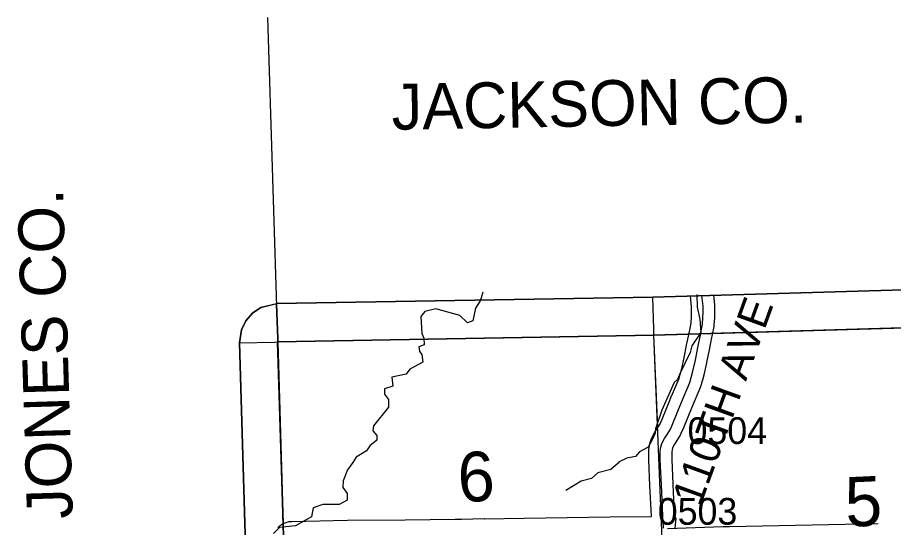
# Model space of a CAD drawing. Extents: x 128.7 to 185.5, y -21.4 to 12.6.
# Drawn here: x 133.107 to 135.402, y 3.861 to 5.197 of the extents above; entities that cross this region are included whole.
import ezdxf

# ---------------------------------------------------------------- set-up
doc = ezdxf.new("R2010")
doc.units = 0
for name, color, linetype in [('tdCoClipBndry', 7, 'Continuous'), ('tdCoCoBndry', 7, 'Continuous'), ('tdCoCoBndryPart', 7, 'Continuous'), ('tdCoCoBndryTxt', 7, 'Continuous'), ('tdCoHydroRiver', 7, 'Continuous'), ('tdCoSecRdNmbr', 7, 'Continuous'), ('tdCoSecRdTxt', 7, 'Continuous'), ('tdCoSecRteBand', 7, 'Continuous'), ('tdCoSecRteCL', 7, 'Continuous'), ('tdCoSectLine', 7, 'Continuous'), ('tdCoSectLinePart', 7, 'Continuous'), ('tdCoSectNmbr', 7, 'Continuous'), ('tdCoSurfGravel', 7, 'Continuous'), ('tdCoSurfLNO', 7, 'Continuous'), ('tdCoTwpBndryShd', 7, 'Continuous')]:
    doc.layers.add(name, color=color, linetype=linetype)

msp = doc.modelspace()

# ---------------------------------------------------------------- linework, layer by layer
at = {"layer": 'tdCoClipBndry'}
msp.add_lwpolyline([(134.0612, -7.7025), (133.8962, -2.6807), (133.6887, 4.3446), (133.6938, 4.3792), (133.7053, 4.4028), (133.7226, 4.4226), (133.7445, 4.4372), (133.7868, 4.4475), (134.771, 4.4649), (135.7559, 4.4935), (136.7866, 4.5129), (139.7725, 4.5879), (146.7594, 4.806), (147.7608, 4.8492), (149.7557, 4.9088), (150.75, 4.946), (153.7332, 5.0633)], dxfattribs=at)
at = {"layer": 'tdCoCoBndry'}
for p, q in [((133.7889, 4.3556), (133.7861, 4.4473)), ((133.7861, 4.4473), (133.7889, 4.3556)), ((134.7737, 4.365), (135.7592, 4.3936)), ((135.7592, 4.3936), (134.7737, 4.365)), ((133.789, 4.3475), (134.7737, 4.365)), ((134.7737, 4.365), (133.789, 4.3475)), ((133.789, 4.3475), (133.7889, 4.3556)), ((133.7889, 4.3556), (133.789, 4.3475)), ((133.8192, 3.3421), (133.789, 4.3475)), ((133.789, 4.3475), (133.8192, 3.3421))]:
    msp.add_line(p, q, dxfattribs=at)
for points in [[(139.7725, 4.5879), (136.7866, 4.5129), (135.7559, 4.4935), (134.771, 4.4649), (133.7868, 4.4475), (133.7861, 4.4473), (133.7889, 4.3556), (133.789, 4.3475), (134.7737, 4.365), (135.7592, 4.3936), (135.7859, 4.3937), (136.7735, 4.4131), (136.7891, 4.4129), (137.7728, 4.4375)], [(133.7886, 4.3475), (134.7733, 4.365), (135.7588, 4.3936), (135.7855, 4.3937), (136.7732, 4.4131), (136.7888, 4.4129), (137.7724, 4.4375)], [(134.1615, -7.6994), (134.1297, -6.7029), (134.1294, -6.6932), (134.095, -5.6895), (134.0611, -4.6883), (134.0307, -3.6816), (133.9965, -2.6778), (133.9676, -1.6731), (133.9395, -0.6703), (133.9071, 0.3357), (133.8784, 1.3376), (133.8476, 2.341), (133.8192, 3.3421), (133.789, 4.3475), (134.7737, 4.365), (135.7592, 4.3936), (135.7859, 4.3937), (136.7735, 4.4131), (136.7891, 4.4129), (137.7728, 4.4375)], [(133.7886, 4.3475), (133.8188, 3.3421), (133.8473, 2.341), (133.878, 1.3376), (133.9067, 0.3357), (133.9391, -0.6703), (133.9673, -1.6731), (133.9961, -2.6778), (134.0303, -3.6816), (134.0608, -4.6883), (134.0947, -5.6895), (134.129, -6.6932), (134.1293, -6.7029), (134.1612, -7.6994), (134.1875, -8.683), (134.2186, -9.7062), (134.2417, -10.7094), (134.275, -11.7191), (134.2997, -12.7212), (134.329, -13.723)]]:
    msp.add_lwpolyline(points, dxfattribs=at)
msp.add_lwpolyline([(133.7861, 4.4473), (133.7445, 4.4372), (133.7226, 4.4226), (133.7053, 4.4028), (133.6938, 4.3792), (133.6887, 4.3446), (133.8665, -1.6741), (133.9676, -1.6731), (133.9395, -0.6703), (133.9071, 0.3357), (133.8784, 1.3376), (133.8476, 2.341), (133.8192, 3.3421), (133.789, 4.3475), (133.7889, 4.3556)], close=True, dxfattribs=at)
at = {"layer": 'tdCoCoBndryPart'}
for points in [[(133.7623, 5.1969), (133.7886, 4.3556), (133.7886, 4.3475)], [(134.9269, 4.3694), (135.7588, 4.3936), (135.7855, 4.3937), (136.0567, 4.3991)], [(133.7886, 4.3475), (134.7733, 4.365), (134.8654, 4.3676)], [(133.8029, 3.8715), (133.7886, 4.3475)]]:
    msp.add_lwpolyline(points, dxfattribs=at)
at = {"layer": 'tdCoHydroRiver'}
for points in [[(134.3266, 4.4777), (134.326, 4.477), (134.3188, 4.4547), (134.3067, 4.4354), (134.2998, 4.4021), (134.2858, 4.3969), (134.2662, 4.4169), (134.2026, 4.4339), (134.1744, 4.4268), (134.1637, 4.4138), (134.1666, 4.3697), (134.1717, 4.3572), (134.1722, 4.3399), (134.1582, 4.3347), (134.1601, 4.3222), (134.1667, 4.3145), (134.1688, 4.294), (134.1347, 4.2756), (134.1256, 4.2627), (134.0879, 4.2553), (134.0902, 4.2317), (134.0683, 4.2247), (134.0687, 4.2106), (134.0786, 4.1966), (134.0792, 4.1761), (134.0396, 4.1276), (134.0384, 4.1149), (134.0482, 4.1026), (134.0486, 4.09), (134.0301, 4.0752), (134.021, 4.0623), (133.9946, 4.0458), (133.9856, 4.0313), (133.9719, 4.012), (133.9602, 3.9832), (133.9591, 3.9658), (133.9706, 3.9504), (133.9711, 3.933), (133.9494, 3.9213), (133.9067, 3.9216), (133.8817, 3.913), (133.8777, 3.8892), (133.8358, 3.8659), (133.7933, 3.8615), (133.778, 3.8452)], [(134.8866, 4.4716), (134.8875, 4.4384), (134.8948, 4.407), (134.8974, 4.3724), (134.8732, 4.3369), (134.869, 4.3195), (134.8422, 4.2634), (134.8363, 4.249), (134.8271, 4.2409), (134.7945, 4.1689), (134.7786, 4.1195), (134.7773, 4.1084), (134.7669, 4.086), (134.7595, 4.0715), (134.7361, 4.0598), (134.7255, 4.0469), (134.7035, 4.0431), (134.6833, 4.033), (134.6802, 4.0297), (134.6617, 4.0134), (134.6273, 4.0045), (134.6103, 3.9898), (134.5837, 3.9827), (134.5434, 3.9578)]]:
    msp.add_lwpolyline(points, dxfattribs=at)
at = {"layer": 'tdCoSecRteBand'}
for points in [[(133.7895, 3.861), (133.791, 3.8627), (133.7927, 3.8642), (133.7951, 3.8662), (133.7969, 3.8677), (133.7988, 3.8689), (133.8015, 3.8706), (133.8035, 3.8718), (133.8056, 3.8727), (133.8085, 3.8739), (133.8106, 3.8748), (133.8128, 3.8754), (133.8159, 3.8762), (133.8181, 3.8767), (133.8204, 3.8769), (133.8235, 3.8772), (133.8247, 3.8773), (133.8258, 3.8774), (133.9716, 3.8801), (133.9717, 3.8801), (133.9718, 3.8801), (134.123, 3.8816), (134.2536, 3.8833), (134.2536, 3.8833), (134.2536, 3.8833), (134.2702, 3.8835), (134.3, 3.8839), (134.3298, 3.8846), (134.3298, 3.8842), (134.3302, 3.8842), (134.4341, 3.8855), (134.6597, 3.889), (134.6598, 3.889), (134.6598, 3.889), (134.7677, 3.8902), (134.7677, 3.8907), (134.7637, 3.9716), (134.7637, 3.9716), (134.7637, 3.9717), (134.7608, 4.0373), (134.7607, 4.038), (134.7607, 4.0386), (134.7607, 4.0608), (134.7607, 4.0628), (134.761, 4.0648), (134.7625, 4.0759), (134.7628, 4.0782), (134.7635, 4.0805), (134.7662, 4.0896), (134.767, 4.0922), (134.7682, 4.0947), (134.7751, 4.1082), (134.7758, 4.1097), (134.7767, 4.111), (134.7834, 4.1214), (134.7907, 4.1329), (134.7958, 4.1451), (134.817, 4.1967), (134.817, 4.1969), (134.8171, 4.197), (134.8399, 4.2516), (134.8432, 4.2622), (134.8471, 4.2779), (134.8533, 4.3054), (134.8597, 4.3385), (134.8597, 4.3387), (134.8598, 4.339), (134.8664, 4.3706), (134.8671, 4.3743), (134.8678, 4.3779), (134.8716, 4.3972), (134.8725, 4.4135), (134.8729, 4.4236), (134.8727, 4.4393), (134.8697, 4.4678)], [(134.9299, 4.4695), (134.9325, 4.4443), (134.9327, 4.4429), (134.9327, 4.4415), (134.9329, 4.4235), (134.933, 4.4226), (134.9329, 4.4218), (134.9324, 4.4107), (134.9324, 4.4105), (134.9324, 4.4104), (134.9314, 4.3919), (134.9313, 4.3898), (134.9309, 4.3877), (134.9267, 4.3664), (134.926, 4.3627), (134.9252, 4.3589), (134.9252, 4.3587), (134.9252, 4.3585), (134.9186, 4.327), (134.9122, 4.2937), (134.9121, 4.2932), (134.912, 4.2927), (134.9056, 4.2643), (134.9055, 4.264), (134.9054, 4.2637), (134.9012, 4.2469), (134.901, 4.2461), (134.9008, 4.2454), (134.8968, 4.2325), (134.8964, 4.2311), (134.8958, 4.2298), (134.8725, 4.1739), (134.8513, 4.1222), (134.8512, 4.1221), (134.8512, 4.1219), (134.845, 4.1073), (134.8441, 4.1052), (134.8428, 4.1031), (134.8342, 4.0893), (134.834, 4.0891), (134.8339, 4.0889), (134.8278, 4.0796), (134.8229, 4.0699), (134.8216, 4.0656), (134.8207, 4.0589), (134.8207, 4.0393), (134.8237, 3.9745), (134.8276, 3.8936), (134.8276, 3.8936), (134.8276, 3.8936), (134.8279, 3.887), (134.8317, 3.8866), (134.8293, 3.8588)]]:
    msp.add_lwpolyline(points, dxfattribs=at)
at = {"layer": 'tdCoSecRteCL'}
msp.add_lwpolyline([(134.7992, 3.8594), (134.7976, 3.8922), (134.7937, 3.9731), (134.7907, 4.0386), (134.7907, 4.0608), (134.7922, 4.0719), (134.7949, 4.0811), (134.8018, 4.0946), (134.8087, 4.1052), (134.8174, 4.119), (134.8235, 4.1336), (134.8447, 4.1854), (134.8682, 4.2414), (134.8721, 4.2542), (134.8763, 4.271), (134.8827, 4.2993), (134.8891, 4.3329), (134.8958, 4.3647), (134.8966, 4.3685), (134.8973, 4.3721), (134.9015, 4.3935), (134.9025, 4.412), (134.9029, 4.4231), (134.9027, 4.4411), (134.8998, 4.4686)], dxfattribs=at)
at = {"layer": 'tdCoSectLine'}
for points in [[(134.7701, 4.4649), (134.773, 4.3813), (134.7733, 4.365)], [(133.7857, 4.4472), (133.7886, 4.3556), (133.7886, 4.3475)], [(134.7733, 4.365), (135.7588, 4.3936)], [(133.7886, 4.3475), (134.7733, 4.365)], [(134.7733, 4.365), (134.8144, 3.3614)], [(133.6887, 4.3447), (133.7805, 4.3469), (133.7886, 4.3475)], [(133.7886, 4.3475), (133.8188, 3.3421)]]:
    msp.add_lwpolyline(points, dxfattribs=at)
at = {"layer": 'tdCoSectLinePart'}
for points in [[(134.7701, 4.4649), (134.773, 4.3813), (134.7733, 4.365)], [(133.7857, 4.4472), (133.7886, 4.3556), (133.7886, 4.3475)], [(134.9269, 4.3694), (135.7588, 4.3936)], [(133.7886, 4.3475), (134.7733, 4.365)], [(134.7733, 4.365), (134.8654, 4.3676)], [(134.7733, 4.365), (134.7833, 4.1219)], [(133.6887, 4.3447), (133.7805, 4.3469), (133.7886, 4.3475)], [(133.7886, 4.3475), (133.8029, 3.8715)]]:
    msp.add_lwpolyline(points, dxfattribs=at)
at = {"layer": 'tdCoSurfGravel'}
for points in [[(134.8966, 4.3685), (134.8973, 4.3721), (134.9015, 4.3935), (134.9025, 4.412), (134.9029, 4.4231), (134.9027, 4.4411), (134.8998, 4.4686)], [(134.7992, 3.8594), (134.7976, 3.8922), (134.7937, 3.9731), (134.7907, 4.0386), (134.7907, 4.0608), (134.7922, 4.0719), (134.7949, 4.0811), (134.8018, 4.0946), (134.8087, 4.1052), (134.8174, 4.119), (134.8235, 4.1336), (134.8447, 4.1854), (134.8682, 4.2414), (134.8721, 4.2542), (134.8763, 4.271), (134.8827, 4.2993), (134.8891, 4.3329), (134.8958, 4.3647), (134.8966, 4.3685)]]:
    msp.add_lwpolyline(points, dxfattribs=at)
at = {"layer": 'tdCoSurfLNO'}
for p, q in [((134.8096, 3.8585), (134.9555, 3.8638)), ((134.9555, 3.8638), (134.9581, 3.8639)), ((134.9581, 3.8639), (134.9625, 3.864)), ((134.9625, 3.864), (134.9724, 3.8642)), ((134.9724, 3.8642), (135.3617, 3.8722))]:
    msp.add_line(p, q, dxfattribs=at)
at = {"layer": 'tdCoTwpBndryShd'}
for points in [[(137.7724, 4.4375), (136.7888, 4.4129), (136.7732, 4.4131), (135.7855, 4.3937), (135.7588, 4.3936), (134.7733, 4.365), (133.7886, 4.3475)], [(133.7886, 4.3475), (133.8188, 3.3421), (133.8473, 2.341), (133.878, 1.3376), (133.9067, 0.3357), (133.9391, -0.6703), (133.9673, -1.6731), (133.9961, -2.6778), (134.0303, -3.6816), (134.0608, -4.6883), (134.0947, -5.6895), (134.129, -6.6932), (134.1293, -6.7029), (134.1612, -7.6994)]]:
    msp.add_lwpolyline(points, dxfattribs=at)

# ---------------------------------------------------------------- texts
at = {"layer": 'tdCoCoBndryTxt'}
for s, rotation, p in [('JACKSON CO.', 1.0134, (134.088, 4.9027)), ('JONES CO.', 91.7209, (133.2525, 3.8853))]:
    msp.add_text(s, height=0.12, rotation=rotation, dxfattribs=at).set_placement(p)
at = {"layer": 'tdCoSecRdNmbr'}
for s, p in [('0504', (134.8623, 4.0798)), ('0503', (134.7843, 3.8684))]:
    msp.add_text(s, height=0.07, rotation=0.1032, dxfattribs=at).set_placement(p)
at = {"layer": 'tdCoSecRdTxt'}
msp.add_text('110TH AVE', height=0.08, rotation=70.053, dxfattribs=at).set_placement((134.8954, 3.9129))
at = {"layer": 'tdCoSectNmbr'}
for s, rotation, p in [('6', 2.655, (134.263, 3.9275)), ('5', 2.6558, (135.2775, 3.8627))]:
    msp.add_text(s, height=0.13, rotation=rotation, dxfattribs=at).set_placement(p)

doc.saveas('drawing.dxf')
